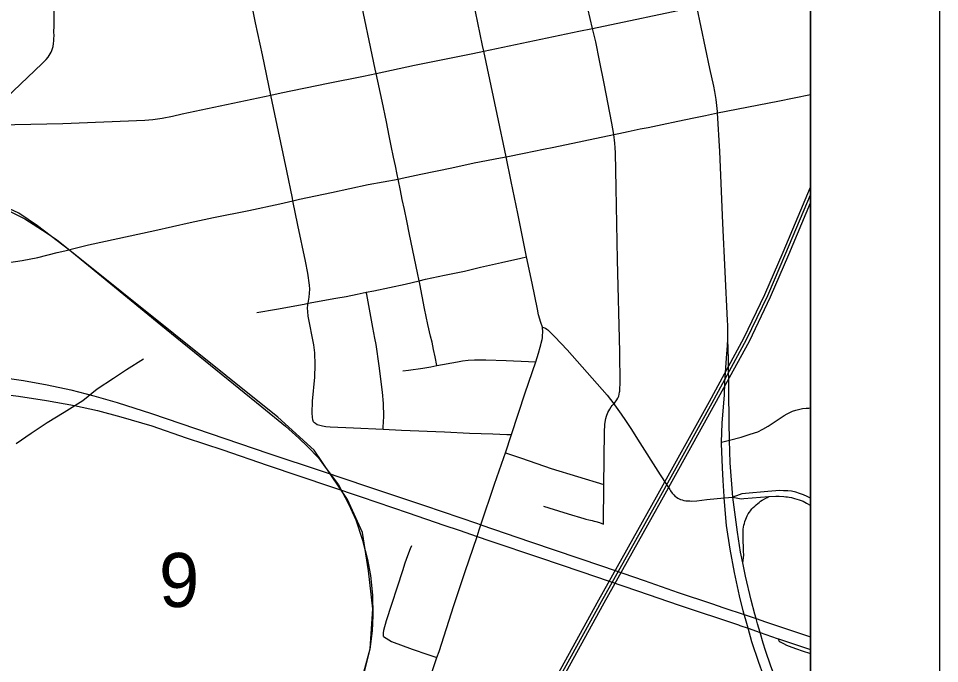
# Model space of a CAD drawing. Extents: x 0 to 34, y 0 to 22.
# Drawn here: x 8.286 to 9, y 19.661 to 20.161 of the extents above; entities that cross this region are included whole.
import ezdxf

# ---------------------------------------------------------------- set-up
doc = ezdxf.new("R2010")
doc.units = 0
for name, color, linetype in [('GM_X_City_Street', 7, 'Continuous'), ('GM_X_County_Road', 7, 'Continuous'), ('GM_X_Interchange_Ramps', 7, 'Continuous'), ('GM_X_Minor_River', 7, 'Continuous'), ('GM_X_Rail_Line', 7, 'Continuous'), ('GM_X_Section_Text', 7, 'Continuous'), ('GM_X_State_Route', 7, 'Continuous'), ('GM_X_Township_Road', 7, 'Continuous'), ('GM_X_Unincorporated', 7, 'Continuous'), ('GM_X_US_Route', 7, 'Continuous'), ('SH_Data', 7, 'Continuous')]:
    doc.layers.add(name, color=color, linetype=linetype)

msp = doc.modelspace()

# ---------------------------------------------------------------- linework, layer by layer
at = {"layer": 'GM_X_City_Street'}
for points in [[(8.61037, 19.89223), (8.60906, 19.89905), (8.60791, 19.90468), (8.60669, 19.91027), (8.60558, 19.91507), (8.60358, 19.92398), (8.60098, 19.93648), (8.59721, 19.95541), (8.5967, 19.95785), (8.59539, 19.964), (8.58926, 19.99364), (8.58715, 20.00431), (8.58528, 20.01299), (8.58368, 20.02087), (8.58228, 20.02773), (8.58042, 20.03668), (8.5797, 20.04018), (8.5783, 20.04691), (8.57695, 20.05348), (8.57509, 20.06233), (8.57344, 20.0702), (8.57133, 20.081), (8.56803, 20.09701), (8.56335, 20.11846), (8.56262, 20.12181), (8.54997, 20.18237)], [(8.73956, 19.76946), (8.73985, 19.80002), (8.73997, 19.81904), (8.74041, 19.84239), (8.74056, 19.84476), (8.74069, 19.84689), (8.74087, 19.84822), (8.74118, 19.84987), (8.74144, 19.85129), (8.74187, 19.85297), (8.74296, 19.85585), (8.74362, 19.85717), (8.74441, 19.85846), (8.74563, 19.86017), (8.74642, 19.86126), (8.74748, 19.86255), (8.74799, 19.8631), (8.74994, 19.86574), (8.75062, 19.86702), (8.75135, 19.86859), (8.7518, 19.86999), (8.75208, 19.8715), (8.75221, 19.87242), (8.75234, 19.87438), (8.75252, 19.87798), (8.75213, 19.90277), (8.75038, 19.97402), (8.74947, 20.0298), (8.74893, 20.05684), (8.74872, 20.06093), (8.7484, 20.06451), (8.74755, 20.07122), (8.74606, 20.08004), (8.74007, 20.1106), (8.73656, 20.12852), (8.73374, 20.14292), (8.73114, 20.15326), (8.72754, 20.16859)], [(8.25454, 20.07875), (8.25958, 20.07875), (8.27071, 20.07875), (8.32071, 20.07967), (8.38411, 20.0823), (8.39026, 20.08284), (8.39758, 20.08388), (8.40561, 20.08538), (8.41322, 20.08705), (8.4818, 20.10167)], [(8.51489, 19.84871), (8.51432, 19.8502), (8.51399, 19.85216), (8.5138, 19.85528), (8.51417, 19.86464), (8.51585, 19.88334), (8.51618, 19.89272), (8.51587, 19.90207), (8.51511, 19.90825), (8.51082, 19.93038), (8.51039, 19.93412), (8.51034, 19.93675), (8.51052, 19.9393), (8.51069, 19.94043), (8.51095, 19.94216), (8.51149, 19.94525), (8.51182, 19.94835), (8.51195, 19.95147), (8.51189, 19.95457), (8.51053, 19.96384), (8.50864, 19.97303), (8.50261, 20.00103), (8.49887, 20.01982)], [(8.47089, 19.93324), (8.48624, 19.93593), (8.50765, 19.93988), (8.51069, 19.94043), (8.5321, 19.94428), (8.54026, 19.94577), (8.5486, 19.94748), (8.55576, 19.94893), (8.56173, 19.95014), (8.58593, 19.95526), (8.5967, 19.95785), (8.60157, 19.95902), (8.61636, 19.96216), (8.63178, 19.96531), (8.64435, 19.96841), (8.66062, 19.972), (8.67544, 19.97532), (8.68002, 19.97635)], [(8.56885, 19.84294), (8.56892, 19.84452), (8.56931, 19.85283), (8.56909, 19.86289), (8.56844, 19.87164), (8.56583, 19.89194), (8.56342, 19.90848), (8.56243, 19.91351), (8.56081, 19.92173), (8.5561, 19.94713), (8.55576, 19.94893)], [(8.61037, 19.89223), (8.62642, 19.89523), (8.63041, 19.89587), (8.6348, 19.89633), (8.6395, 19.89662), (8.64831, 19.89667), (8.66427, 19.89603), (8.68146, 19.89526), (8.68723, 19.895)], [(8.58403, 19.88813), (8.58835, 19.88868), (8.59955, 19.89012), (8.60583, 19.89119), (8.61037, 19.89223)], [(8.83108, 19.83298), (8.83728, 19.83452), (8.84636, 19.83686), (8.85317, 19.839), (8.85908, 19.84099), (8.8631, 19.84309), (8.8671, 19.84534), (8.87731, 19.85208), (8.87949, 19.85349), (8.88184, 19.8548), (8.88401, 19.85591), (8.88615, 19.85685), (8.88873, 19.85771), (8.89167, 19.85855), (8.89387, 19.85899), (8.89673, 19.85925), (8.8986, 19.85934), (8.9, 19.85941)], [(8.51489, 19.84871), (8.5163, 19.84757), (8.51779, 19.84669), (8.51981, 19.84603), (8.52192, 19.84555), (8.52434, 19.84511), (8.52785, 19.8448), (8.54591, 19.84396), (8.56885, 19.84294), (8.58311, 19.8423), (8.61635, 19.841), (8.63574, 19.83999), (8.65386, 19.8393), (8.66473, 19.83896), (8.66825, 19.83885)], [(8.66353, 19.82455), (8.6761, 19.82051), (8.69914, 19.81263), (8.73985, 19.80002)], [(8.69315, 19.78337), (8.69711, 19.78217), (8.71229, 19.77749), (8.72424, 19.77383), (8.72589, 19.77334), (8.72824, 19.77273), (8.73069, 19.77223), (8.73227, 19.77183), (8.73373, 19.77148), (8.73653, 19.77058), (8.73956, 19.76946)], [(8.56913, 19.68232), (8.56923, 19.6849), (8.56947, 19.68725), (8.57155, 19.69477), (8.58398, 19.73364), (8.5859, 19.73947), (8.58795, 19.74516), (8.59013, 19.75053), (8.59108, 19.75277)], [(8.56913, 19.68232), (8.57542, 19.67862), (8.59143, 19.67263), (8.60343, 19.66852), (8.6105, 19.66611)]]:
    msp.add_lwpolyline(points, dxfattribs=at)
at = {"layer": 'GM_X_County_Road'}
for p, q in [((8.73114, 20.15326), (8.81194, 20.17023)), ((8.66353, 19.82455), (8.66825, 19.83885)), ((8.83316, 19.7897), (8.83986, 19.79034))]:
    msp.add_line(p, q, dxfattribs=at)
for points in [[(8.64675, 20.13558), (8.64577, 20.14013), (8.63846, 20.17542), (8.62971, 20.21855)], [(8.4818, 20.10167), (8.47535, 20.13279), (8.46991, 20.15772), (8.46452, 20.18481)], [(8.25454, 20.07875), (8.26505, 20.08873), (8.30472, 20.1262), (8.30612, 20.12772), (8.30764, 20.12933), (8.30915, 20.13101), (8.31007, 20.13236), (8.31083, 20.1336), (8.31153, 20.13479), (8.31212, 20.13609), (8.31272, 20.1377), (8.31315, 20.13937), (8.31342, 20.14154), (8.31364, 20.1437), (8.31369, 20.14564), (8.3138, 20.14737), (8.31374, 20.15083), (8.31379, 20.15482), (8.31399, 20.1694)], [(8.64675, 20.13558), (8.72054, 20.15108), (8.73114, 20.15326)], [(8.56335, 20.11846), (8.59316, 20.12472), (8.6382, 20.13384), (8.64675, 20.13558)], [(8.66403, 20.05393), (8.65719, 20.08695), (8.64675, 20.13558)], [(8.4818, 20.10167), (8.48983, 20.10333), (8.52631, 20.11086), (8.55368, 20.11643), (8.56335, 20.11846)], [(8.49887, 20.01982), (8.49847, 20.02179), (8.49412, 20.04307), (8.48484, 20.087), (8.4818, 20.10167)], [(8.82799, 20.08801), (8.87479, 20.09701), (8.9, 20.10209)], [(8.74755, 20.07122), (8.75138, 20.07202), (8.75872, 20.07351), (8.76812, 20.07542), (8.7741, 20.07665), (8.78502, 20.07889), (8.79715, 20.08139), (8.80949, 20.08393), (8.81855, 20.08592), (8.82799, 20.08801)], [(8.66403, 20.05393), (8.67805, 20.05674), (8.69303, 20.05978), (8.70099, 20.06125), (8.74755, 20.07122)], [(8.58042, 20.03668), (8.58349, 20.03732), (8.59813, 20.04039), (8.62204, 20.04545), (8.63947, 20.0491), (8.65968, 20.05307), (8.66403, 20.05393)], [(8.68002, 19.97635), (8.67309, 20.01004), (8.66802, 20.03471), (8.66403, 20.05393)], [(8.49887, 20.01982), (8.50402, 20.021), (8.52887, 20.02626), (8.55729, 20.0323), (8.58042, 20.03668)], [(8.32229, 19.98113), (8.33022, 19.98308), (8.34064, 19.98563), (8.39194, 19.99691), (8.41917, 20.00292), (8.43736, 20.00678), (8.46472, 20.01217), (8.4889, 20.01755), (8.49887, 20.01982)], [(8.15992, 19.98306), (8.16151, 19.9815), (8.16371, 19.97932), (8.166, 19.97741), (8.16999, 19.97485), (8.17269, 19.9735), (8.17549, 19.97236), (8.17838, 19.97141), (8.18133, 19.97067), (8.18432, 19.97011), (8.19038, 19.96955), (8.20274, 19.96896), (8.21823, 19.96878), (8.23991, 19.96908), (8.25847, 19.97012), (8.27696, 19.97184), (8.28919, 19.97356), (8.30131, 19.97595), (8.31634, 19.97966), (8.32229, 19.98113)], [(8.69221, 19.92206), (8.69104, 19.92556), (8.68929, 19.93142), (8.68832, 19.93578), (8.68422, 19.95595), (8.68002, 19.97635)], [(8.68723, 19.895), (8.68926, 19.90174), (8.69061, 19.9065), (8.69103, 19.90817), (8.69134, 19.90947), (8.69202, 19.91229), (8.69228, 19.91381), (8.69235, 19.91544), (8.69246, 19.91818), (8.69221, 19.92206)], [(8.69221, 19.92206), (8.69457, 19.92115), (8.69556, 19.92046), (8.69642, 19.91976), (8.69916, 19.91715), (8.70177, 19.91455), (8.71149, 19.90429), (8.74233, 19.86917), (8.74748, 19.86255)], [(8.66825, 19.83885), (8.67892, 19.87119), (8.68723, 19.895)], [(8.74748, 19.86255), (8.74811, 19.86175), (8.75332, 19.85447), (8.75675, 19.84967), (8.76128, 19.84281), (8.76594, 19.83526), (8.78339, 19.8076), (8.78828, 19.80015), (8.79091, 19.79623)], [(8.6105, 19.66611), (8.61212, 19.67089), (8.62356, 19.70633), (8.63236, 19.73284), (8.64157, 19.7599), (8.64335, 19.76515), (8.6446, 19.76892), (8.65521, 19.80051), (8.66236, 19.82102), (8.66353, 19.82455)], [(8.79091, 19.79623), (8.79156, 19.79525), (8.79291, 19.79345), (8.79405, 19.79206), (8.79524, 19.79087), (8.79603, 19.79023), (8.79711, 19.78954), (8.79829, 19.78898), (8.79919, 19.78862), (8.80046, 19.78823), (8.80192, 19.78782), (8.80328, 19.78758), (8.80467, 19.78744), (8.80635, 19.78737), (8.80774, 19.78734), (8.81191, 19.78757), (8.81953, 19.78842), (8.83316, 19.7897)], [(8.57048, 19.55363), (8.58255, 19.58494), (8.59107, 19.60833), (8.59601, 19.6231), (8.6105, 19.66611)]]:
    msp.add_lwpolyline(points, dxfattribs=at)
at = {"layer": 'GM_X_Interchange_Ramps'}
for points in [[(8.9, 19.78947), (8.8973, 19.79095), (8.89446, 19.79221), (8.89153, 19.79327), (8.88853, 19.79422), (8.88513, 19.79485), (8.88238, 19.79514), (8.87897, 19.79532), (8.87615, 19.79538), (8.86682, 19.79481), (8.84968, 19.79322), (8.84669, 19.79284), (8.84478, 19.79223), (8.83986, 19.79034)], [(8.83986, 19.79034), (8.84506, 19.78933), (8.84669, 19.78913), (8.84822, 19.78926), (8.86759, 19.79086)], [(8.84743, 19.73954), (8.848, 19.74336), (8.84821, 19.74561), (8.84819, 19.74817), (8.84784, 19.75997), (8.84777, 19.76234), (8.8479, 19.76548), (8.84813, 19.76698), (8.84838, 19.76856), (8.84872, 19.76998), (8.8492, 19.77157), (8.84985, 19.77329), (8.85035, 19.77446), (8.85091, 19.77579), (8.85177, 19.77731), (8.85263, 19.7786), (8.85348, 19.77981), (8.85461, 19.78129), (8.8556, 19.78223), (8.85678, 19.78332), (8.85785, 19.78435), (8.85908, 19.78543), (8.8602, 19.78627), (8.86121, 19.78712), (8.86241, 19.78796), (8.86636, 19.79018), (8.86759, 19.79086), (8.87311, 19.79113), (8.87573, 19.79098), (8.87926, 19.79078), (8.88078, 19.79063), (8.88206, 19.79051), (8.88347, 19.79031), (8.88535, 19.78995), (8.88768, 19.78934), (8.89125, 19.78822), (8.8942, 19.78711), (8.89698, 19.78578), (8.89965, 19.78425), (8.9, 19.78401)], [(8.87509, 19.68059), (8.87527, 19.67972), (8.87577, 19.67894), (8.87655, 19.67827), (8.87905, 19.67688), (8.88138, 19.67566), (8.88561, 19.67406), (8.88909, 19.67287), (8.89347, 19.67139), (8.9, 19.66917)]]:
    msp.add_lwpolyline(points, dxfattribs=at)
at = {"layer": 'GM_X_Minor_River'}
msp.add_lwpolyline([(8.28436, 19.8319), (8.29604, 19.83995), (8.30849, 19.84801), (8.32169, 19.85607), (8.33602, 19.86528), (8.34732, 19.87409), (8.35976, 19.88253), (8.36994, 19.88905), (8.38314, 19.89749)], dxfattribs=at)
at = {"layer": 'GM_X_Rail_Line'}
for points in [[(8.50556, 19.47488), (8.54897, 19.63665), (8.55883, 19.67282), (8.5608, 19.70373), (8.55752, 19.73332), (8.55291, 19.76291), (8.54108, 19.78856), (8.51543, 19.8267), (8.48715, 19.85235), (8.32603, 19.98124), (8.30104, 20.00031), (8.28658, 20.01018), (8.26225, 20.02136), (8.23002, 20.02991), (8.17347, 20.03648), (7.93541, 20.05555), (7.91905, 20.05752)], [(8.42712, 18.98036), (8.43359, 19.00347), (8.4533, 19.05412), (8.53216, 19.25558), (8.58729, 19.39608), (8.61213, 19.46075), (8.63198, 19.51134), (8.64379, 19.53981), (8.65647, 19.56535), (8.67101, 19.59304), (8.68569, 19.61947), (8.69776, 19.64136), (8.73605, 19.7107), (8.78054, 19.79055), (8.82175, 19.86452), (8.84841, 19.91337), (8.8647, 19.94732), (8.8788, 19.98015), (8.9, 20.03044)], [(7.88643, 17.59932), (7.90898, 17.6604), (8.00201, 17.89866), (8.29237, 18.63494), (8.4135, 18.9454), (8.4555, 19.05327), (8.53436, 19.25473), (8.58949, 19.39524), (8.61432, 19.45991), (8.63417, 19.51046), (8.64593, 19.53884), (8.65857, 19.56429), (8.67308, 19.59193), (8.68775, 19.61833), (8.69982, 19.64023), (8.73811, 19.70956), (8.7826, 19.78941), (8.82382, 19.86339), (8.85051, 19.9123), (8.86685, 19.94635), (8.88097, 19.97923), (8.9, 20.02438)], [(7.75733, 17.27239), (7.85176, 17.51498), (7.91117, 17.65953), (8.0042, 17.8978), (8.29457, 18.63409), (8.4157, 18.94455), (8.45769, 19.05242), (8.53655, 19.25388), (8.59169, 19.39439), (8.61652, 19.45906), (8.63635, 19.50959), (8.64808, 19.53787), (8.66067, 19.56322), (8.67516, 19.59082), (8.68982, 19.6172), (8.70189, 19.6391), (8.74017, 19.70843), (8.78466, 19.78827), (8.82588, 19.86226), (8.85261, 19.91123), (8.86899, 19.94538), (8.88314, 19.97832), (8.9, 20.01832)], [(8.27933, 20.01167), (8.29122, 20.00577), (8.30475, 19.99718), (8.3156, 19.98989), (8.32757, 19.98035), (8.35793, 19.95545), (8.39663, 19.92387), (8.43922, 19.88925), (8.47488, 19.86028), (8.4931, 19.84527), (8.50342, 19.83607), (8.51028, 19.82956), (8.51861, 19.82072), (8.52398, 19.8136), (8.53413, 19.79981), (8.54194, 19.78506), (8.54756, 19.77264), (8.55296, 19.75702), (8.5568, 19.74196), (8.55893, 19.7296), (8.56049, 19.71441), (8.56077, 19.69864), (8.56035, 19.68671), (8.5585, 19.67251), (8.55083, 19.64169)]]:
    msp.add_lwpolyline(points, dxfattribs=at)
at = {"layer": 'GM_X_State_Route'}
for p, q in [((8.83561, 19.90766), (8.83601, 19.91254)), ((8.87509, 19.68059), (8.9, 19.67238))]:
    msp.add_line(p, q, dxfattribs=at)
for points in [[(8.9, 19.05919), (8.9, 20.89996), (6.88573, 20.89996)], [(8.83601, 19.91254), (8.83597, 19.91666), (8.83581, 19.92344), (8.83565, 19.92703), (8.83193, 20.00245), (8.82983, 20.05801), (8.82799, 20.08801), (8.82793, 20.08901), (8.82741, 20.0936), (8.82685, 20.09831), (8.82581, 20.10433), (8.82497, 20.10867), (8.82204, 20.12219), (8.81194, 20.17023), (8.80825, 20.18912), (8.80509, 20.20424), (8.80158, 20.22103), (8.79527, 20.25346)], [(8.86671, 19.64381), (8.85991, 19.66237), (8.85462, 19.6782), (8.85159, 19.68879), (8.84953, 19.69598), (8.84867, 19.69936), (8.84789, 19.7024), (8.84496, 19.7139), (8.84099, 19.73195), (8.83765, 19.75012), (8.83499, 19.7684), (8.83316, 19.7897), (8.8331, 19.79072), (8.83233, 19.80318), (8.83177, 19.81305), (8.83104, 19.83193), (8.83108, 19.83298), (8.83154, 19.84765), (8.83324, 19.86964), (8.83354, 19.87909), (8.83482, 19.89789), (8.83561, 19.90766)], [(8.86523, 19.67171), (8.86334, 19.67733), (8.86086, 19.68554), (8.85881, 19.69233), (8.85776, 19.6963), (8.85683, 19.69979), (8.85399, 19.71049), (8.84951, 19.72927), (8.84743, 19.73954), (8.84577, 19.7477), (8.84337, 19.76332), (8.83986, 19.79034), (8.83771, 19.81699), (8.83728, 19.83452), (8.83695, 19.84813), (8.83673, 19.87324), (8.83636, 19.89692), (8.83601, 19.91254)], [(8.25434, 19.87138), (8.27143, 19.87031), (8.28635, 19.86854), (8.30788, 19.86522), (8.32974, 19.86126), (8.34759, 19.85736), (8.36545, 19.85248), (8.38954, 19.84547), (8.41627, 19.83638), (8.4446, 19.82691), (8.4789, 19.8152), (8.5044, 19.80664), (8.55169, 19.79054), (8.58809, 19.77819), (8.61582, 19.76862), (8.62763, 19.76466), (8.64157, 19.7599), (8.65158, 19.75653), (8.68995, 19.74359), (8.72196, 19.73263), (8.76594, 19.7177), (8.79833, 19.70668), (8.84419, 19.69139), (8.84511, 19.69107)], [(8.84511, 19.69107), (8.85159, 19.68879), (8.86086, 19.68554), (8.87427, 19.68085), (8.87509, 19.68059)], [(8.9, 19.58772), (8.89928, 19.58919), (8.89034, 19.60788), (8.88287, 19.62484), (8.87594, 19.64192), (8.86934, 19.65952), (8.86523, 19.67171)]]:
    msp.add_lwpolyline(points, dxfattribs=at)
at = {"layer": 'GM_X_Township_Road'}
msp.add_lwpolyline([(8.9, 17.26338), (8.9, 20.89996), (5.78179, 20.89996)], dxfattribs=at)
at = {"layer": 'GM_X_Unincorporated'}
msp.add_lwpolyline([(8.9, 19.27567), (8.9, 20.28618), (7.90836, 20.28708), (7.90787, 19.27209)], close=True, dxfattribs=at)
at = {"layer": 'GM_X_US_Route'}
msp.add_line((8.87509, 19.68059), (8.9, 19.67238), dxfattribs=at)
for points in [[(8.27179, 19.88327), (8.29021, 19.88055), (8.30852, 19.87721), (8.32672, 19.87331), (8.34477, 19.86876), (8.36266, 19.86361), (8.38926, 19.85512), (8.48031, 19.82419), (8.52152, 19.81046), (8.55678, 19.79855), (8.60091, 19.78377), (8.64203, 19.76981), (8.6446, 19.76892), (8.68313, 19.75579), (8.73892, 19.73682), (8.77118, 19.72573), (8.79752, 19.71648), (8.82331, 19.70786), (8.83282, 19.70469), (8.84867, 19.69936), (8.85776, 19.6963), (8.86517, 19.69383), (8.89525, 19.68376), (8.9, 19.68212)], [(8.25434, 19.87138), (8.27143, 19.87031), (8.28635, 19.86854), (8.30788, 19.86522), (8.32974, 19.86126), (8.34759, 19.85736), (8.36545, 19.85248), (8.38954, 19.84547), (8.41627, 19.83638), (8.4446, 19.82691), (8.4789, 19.8152), (8.5044, 19.80664), (8.55169, 19.79054), (8.58809, 19.77819), (8.61582, 19.76862), (8.62763, 19.76466), (8.64157, 19.7599), (8.65158, 19.75653), (8.68995, 19.74359), (8.72196, 19.73263), (8.76594, 19.7177), (8.79833, 19.70668), (8.84419, 19.69139), (8.84511, 19.69107)], [(8.84511, 19.69107), (8.85159, 19.68879), (8.86086, 19.68554), (8.87427, 19.68085), (8.87509, 19.68059)]]:
    msp.add_lwpolyline(points, dxfattribs=at)
at = {"layer": 'SH_Data'}
for p, q in [((9, 20.99996), (9, 13.99996)), ((8.9, 20.89996), (8.9, 14.09996))]:
    msp.add_line(p, q, dxfattribs=at)

# ---------------------------------------------------------------- texts
at = {"layer": 'GM_X_Section_Text'}
msp.add_text('9', height=0.04186, rotation=0.00001, dxfattribs=at).set_placement((8.39515, 19.70526))

doc.saveas('drawing.dxf')
